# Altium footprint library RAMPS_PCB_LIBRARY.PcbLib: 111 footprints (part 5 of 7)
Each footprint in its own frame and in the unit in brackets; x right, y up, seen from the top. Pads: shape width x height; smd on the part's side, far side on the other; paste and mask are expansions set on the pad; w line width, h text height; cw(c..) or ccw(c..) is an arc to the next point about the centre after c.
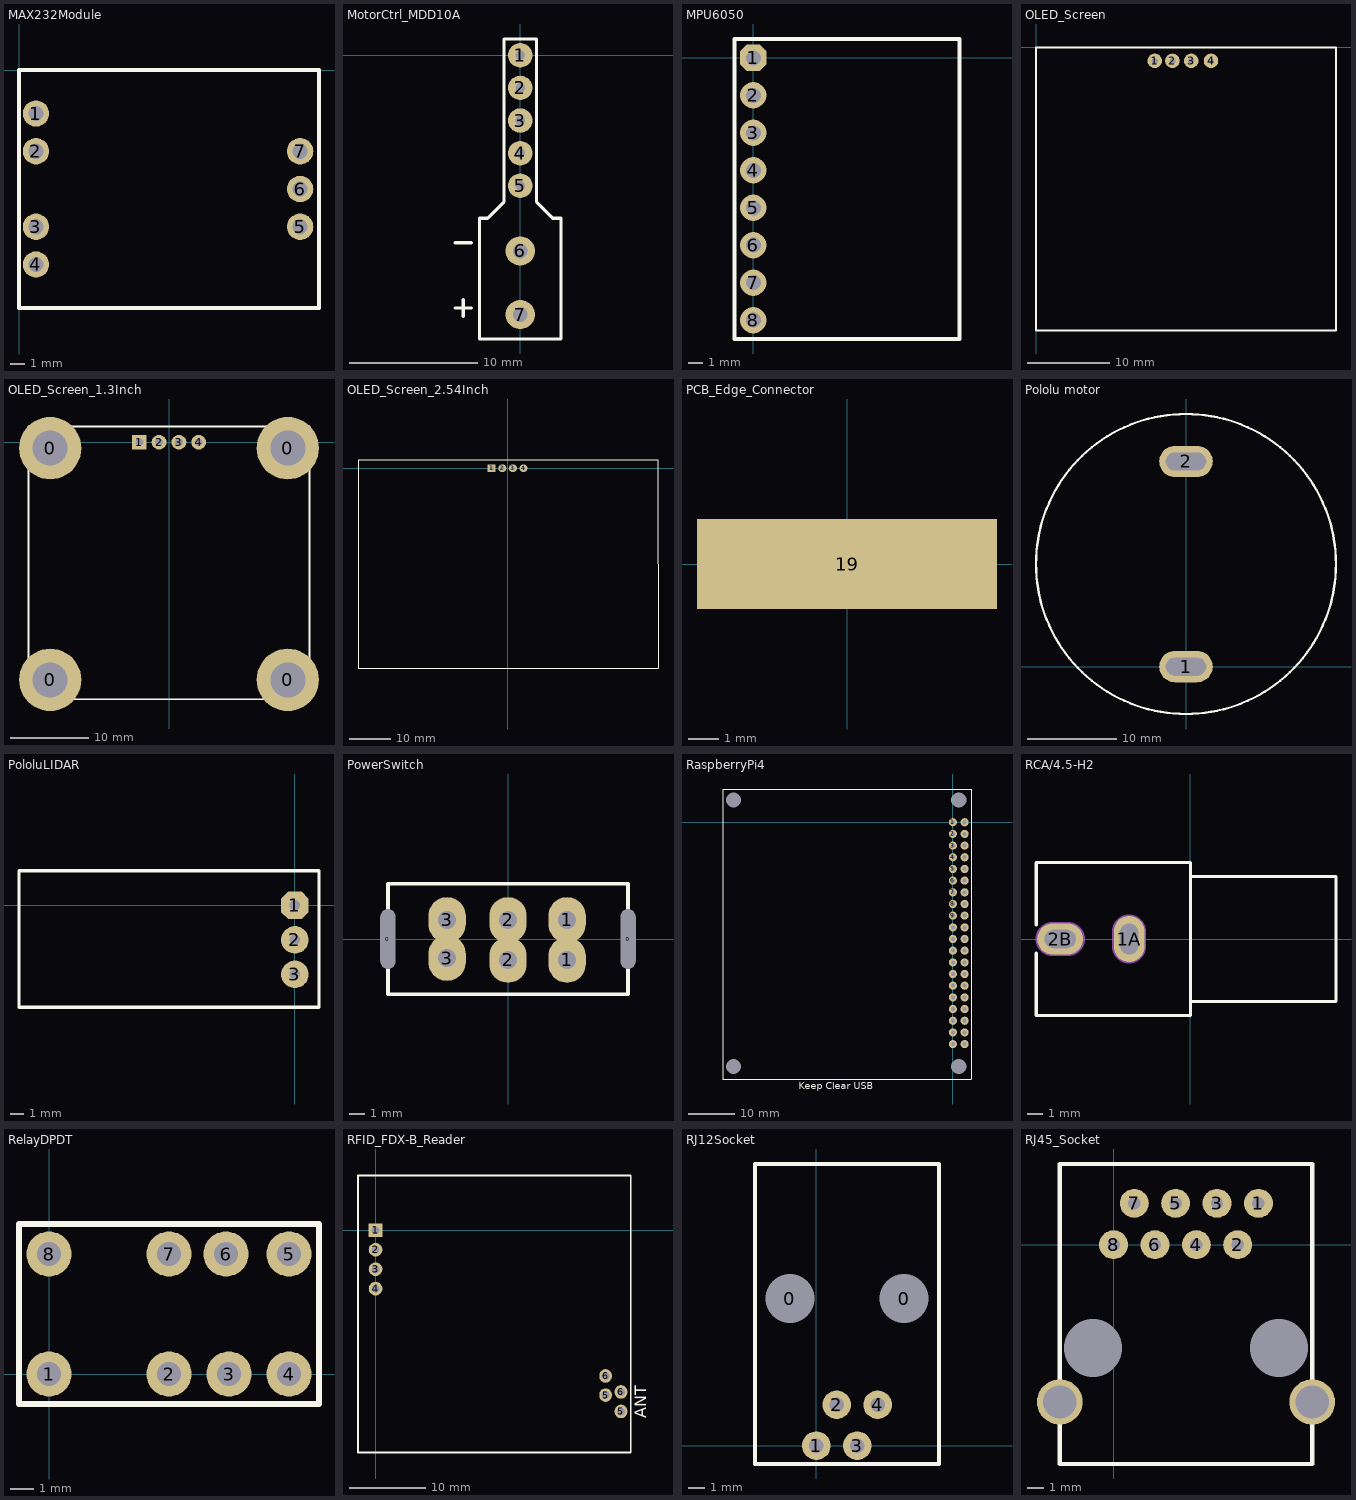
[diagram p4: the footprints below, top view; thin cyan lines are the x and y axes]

## MAX232Module [mil]
pads (7):
  round 70 hole 40: 1(45,-115) 2(45,-215) 3(45,-415) 4(45,-515) 5(745,-415) 6(745,-315) 7(745,-215)
Top Overlay:
  lines w10: 0,-630 0,0 795,0 795,-630 0,-630

## MotorCtrl_MDD10A [mil]
pads (7):
  round 75 hole 30: 1(0,0) 2(0,-100) 3(0,-200) 4(0,-300) 5(0,-400)
  round 90 hole 45: 6(0,-600) 7(0,-795)
Top Overlay:
  lines w10: -200,-775 -150,-775 ; -200,-575 -150,-575 ; -175,-800 -175,-750 ; -125,-870 125,-870 125,-525 125,-500 100,-500 50,-450 50,50 -50,50 -50,-450 -100,-500 -125,-500 -125,-525 -125,-870

## MPU6050 [mil]
pads (8):
  oct 70x70 hole 40: 1(0,0)
  round 70 hole 40: 2(0,-100) 3(0,-200) 4(0,-300) 5(0,-400) 6(0,-500) 7(0,-600) 8(0,-700)
Top Overlay:
  lines w10: -50,-750 550,-750 550,50 -50,50 -50,-750

## OLED_Screen [mil]
pads (4):
  round 70 hole 30: 1(570,-65) 2(655,-65) 3(745,-65) 4(840,-65)
Top Overlay:
  lines w10: 0,-1360 1440,-1360 1440,0 0,0 0,-1360

## OLED_Screen_1.3Inch [mm]
pads (8):
  round 8 hole 4.5: 0(-15.24,-30.48) 0(-15.24,-0.762) 0(15.24,-30.48) 0(15.24,-0.762)
  rect 1.905x1.905 hole 1.016: 1(-3.81,0)
  round 1.905 hole 1.016: 2(-1.27,0) 3(1.27,0) 4(3.81,0)
Top Overlay:
  lines w0.254: -18.034,-32.968 -18.034,2.032 18,2.032 18,-32.968 -18.034,-32.968

## OLED_Screen_2.54Inch [mil]
pads (4):
  rect 75x75 hole 40: 1(-150,0)
  round 75 hole 40: 2(-50,0) 3(50,0) 4(150,0)
Top Overlay:
  lines w10: -1410,-1885 1417.32,-1885 1417.32,80 -1410,80 -1410,-1885

## PCB_Edge_Connector [mm]
pads (1):
  rect 10x3 smd: 19(0,0)

## Pololu motor [mm]
pads (2):
  oval 6x3.5 hole 2 slot 4.5 at 0 deg: 1(0,0) 2(0,22.987)
Top Overlay:
  circle w0.254: c0,11.5 r16.8

## PololuLIDAR [mil]
pads (3):
  oct 80x80 hole 30: 1(0,0)
  round 80 hole 30: 2(0,-100) 3(0,-200)
Top Overlay:
  lines w10: -800,-295 -800,100 70,100 70,-295 -800,-295

## PowerSwitch [mm]
pads (8):
  round 0.5 hole 1 slot 4 at 90 deg: 0(-8.001,0) 0(8.001,0)
  oval 2.5x3.048 hole 1.2: 1(3.937,-1.397) 1(3.937,1.27) 2(0,-1.397) 2(0,1.27) 3(-4.064,-1.27) 3(-4.064,1.27)
Top Overlay:
  lines w0.254: 4.953,-3.683 8.001,-3.683 8.001,3.683 5.08,3.683 -5.08,3.683 -8.001,3.683 -8.001,-3.683 -5.08,-3.683 5.08,-3.683

## RaspberryPi4 [mil]
pads (44):
  round 70 hole 35: 1(0,0) 2(0,-100) 3(0,-200) 4(0,-300) 5(0,-400) 6(0,-500) 7(0,-600) 8(0,-700) 9(0,-800) 10(0,-900) 11(0,-1000) 12(0,-1100) 13(0,-1200) 14(0,-1300) 15(0,-1400) 16(0,-1500) 17(0,-1600) 18(0,-1700) 19(0,-1800) 20(0,-1900) 21(100,-1900) 22(100,-1800) 23(100,-1700) 24(100,-1600) 25(100,-1500) 26(100,-1400) 27(100,-1300) 28(100,-1200) 29(100,-1100) 30(100,-1000) 31(100,-900) 32(100,-800) 33(100,-700) 34(100,-600) 35(100,-500) 36(100,-400) 37(100,-300) 38(100,-200) 39(100,-100) 40(100,0)
  round 60 hole 129.92: 11(-1879.13,-2091.73) 11(-1879.13,191.73) 11(50,-2091.73) 11(50,191.73)
Top Overlay:
  lines w10: -1970,-2200 155,-2200 155,285 -1970,285 -1970,-2200
  text "Keep Clear USB" at -1320,-2285.01 h60

## RCA/4.5-H2 [mm] "Two Conductor Jack (RCA), Right Angle, Thru-Hole, Body 10 x 10 x 13 mm (WxTxH)"
height 13
pads (2):
  oval 2x3 hole 1.2 slot 2.032 at 90 deg: 1A(-4,0)
  oval 3x2.032 hole 1.2 slot 2.032 at 0 deg: 2B(-8.496,0)
Top Overlay:
  lines w0.2: -10.075,5 -0.018,5 ; -10.057,-0.92 -10.057,-5 0,-5 0,5 ; -10.057,0.92 -10.057,5 ; 0,-4.065 9.5,-4.065 9.5,4.065 0,4.065
Mechanical 2:
  lines w2.216: -8.996,0 -7.996,0 ; -4,-0.5 -4,0.5

## RelayDPDT [mil]
pads (8):
  round 75 hole 40: 1(0,0) 2(200,0) 3(300,0) 4(400,0) 5(400,200) 6(295,200) 7(200,200) 8(0,200)
Top Overlay:
  lines w10: -50,-50 450,-50 450,250 -50,250 -50,-50

## RFID_FDX-B_Reader [mil]
pads (8):
  rect 70x70 hole 40: 1(0,0)
  round 70 hole 40: 2(0,-100) 3(0,-200) 4(0,-300)
  oval 65x70 hole 40: 5(1181.1,-846.46) 5(1260,-930) 6(1181.1,-748.03) 6(1260,-830)
Top Overlay:
  lines w10: -90,-1140 -90,280 1310,280 1310,-1140 -90,-1140
  text "ANT" at 1390,-965 h60

## RJ12Socket [mil]
pads (6):
  round 60 hole 120: 0(-65,360) 0(215,360)
  round 70 hole 35: 1(0,0) 2(50,100) 3(100,0) 4(150,100)
Top Overlay:
  lines w10: -150,-45 300,-45 300,690 -150,690 -150,-45

## RJ45_Socket [mil]
pads (12):
  round 70 hole 30: 1(350,100) 2(300,0) 3(250,100) 4(200,0) 5(150,100) 6(100,0) 7(50,100) 8(0,0)
  round 110 hole 80: ""(-130,-380) ""(480,-380)
  round 60 hole 140: ""(-50,-250) ""(400,-250)
Top Overlay:
  lines w10: -130,-530 -130,195 480,195 480,-530 -130,-530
